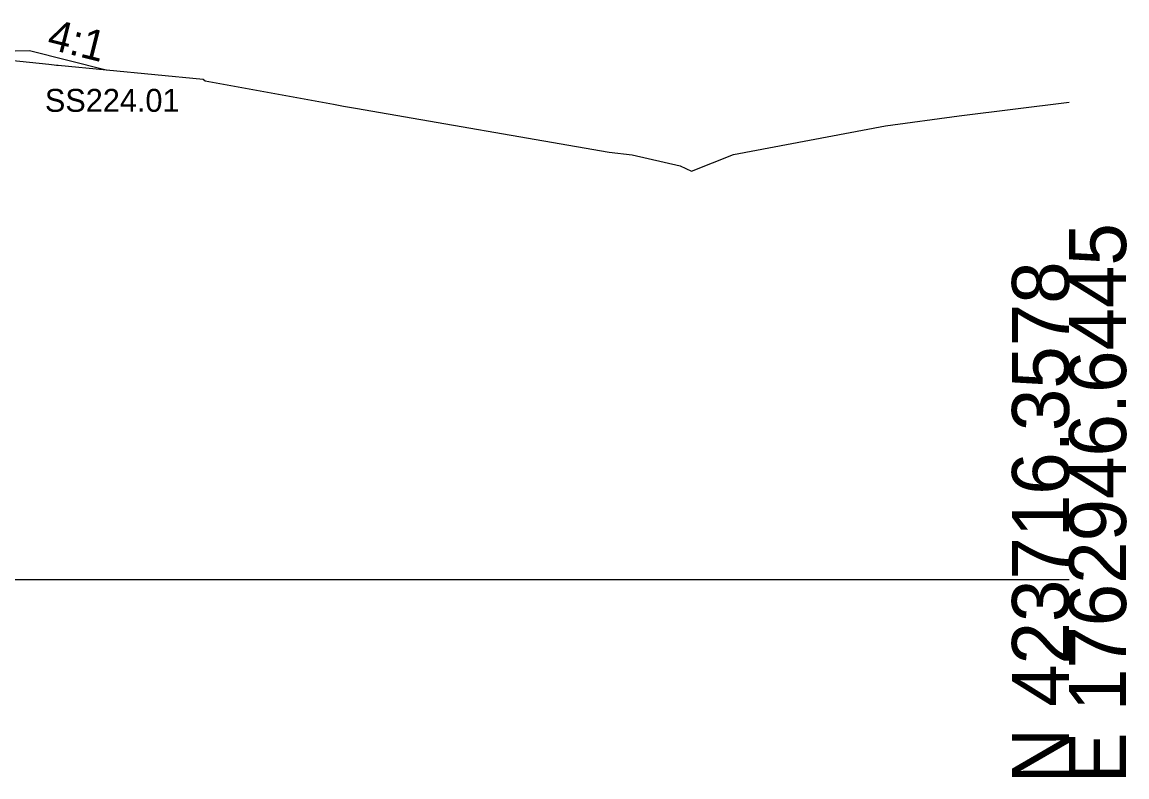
# Model space of a CAD drawing. Extents: x -26 to 3203, y -11010 to 4024.
# Drawn here: x 1148.6 to 1202.8, y -509.7 to -472.6 of the extents above; entities that cross this region are included whole.
import ezdxf

# ---------------------------------------------------------------- set-up
doc = ezdxf.new("R2010")
doc.units = 0
for name, color, linetype in [('Exist Cross Section Cell', 7, 'Continuous'), ('Exist XS Ground Line', 7, 'Continuous'), ('Prop CMT Slope Grass', 7, 'Continuous'), ('Prop XS Side Slope Text', 7, 'Continuous'), ('Prop XS SS Elevation Text', 7, 'Continuous'), ('Scratch_Level_0', 7, 'Continuous')]:
    doc.layers.add(name, color=color, linetype=linetype)

msp = doc.modelspace()

# ---------------------------------------------------------------- linework, layer by layer
at = {"layer": 'Exist Cross Section Cell'}
msp.add_line((1100, -500), (1200, -500), dxfattribs=at)
at = {"layer": 'Exist XS Ground Line'}
msp.add_lwpolyline([(1145.494, -474.255), (1149.934, -474.715), (1150.197, -474.742), (1150.316, -474.755), (1150.381, -474.762), (1150.392, -474.763), (1157.515, -475.441), (1157.604, -475.523), (1163.911, -476.682), (1164.407, -476.772), (1164.989, -476.878), (1177.433, -479.035), (1178.563, -479.163), (1180.913, -479.705), (1181.472, -479.96), (1183.529, -479.15), (1190.991, -477.741), (1194.606, -477.255), (1200, -476.571)], dxfattribs=at)
msp.add_lwpolyline([(1145.494, -474.255), (1149.934, -474.715), (1150.197, -474.742), (1150.316, -474.755), (1150.381, -474.762), (1150.392, -474.763), (1157.515, -475.441), (1157.604, -475.523), (1163.911, -476.682), (1164.407, -476.772), (1164.989, -476.878), (1177.433, -479.035), (1178.563, -479.163), (1180.913, -479.705), (1181.472, -479.96), (1183.529, -479.15), (1190.991, -477.741), (1194.606, -477.255), (1200, -476.571)], dxfattribs=at)
msp.add_lwpolyline([(1145.494, -474.255), (1149.934, -474.715), (1150.197, -474.742), (1150.316, -474.755), (1150.381, -474.762), (1150.392, -474.763), (1157.515, -475.441), (1157.604, -475.523), (1163.911, -476.682), (1164.407, -476.772), (1164.989, -476.878), (1177.433, -479.035), (1178.563, -479.163), (1180.913, -479.705), (1181.472, -479.96), (1183.529, -479.15), (1190.991, -477.741), (1194.606, -477.255), (1200, -476.571)], dxfattribs=at)
msp.add_lwpolyline([(1145.494, -474.255), (1149.934, -474.715), (1150.197, -474.742), (1150.316, -474.755), (1150.381, -474.762), (1150.392, -474.763), (1157.515, -475.441), (1157.604, -475.523), (1163.911, -476.682), (1164.407, -476.772), (1164.989, -476.878), (1177.433, -479.035), (1178.563, -479.163), (1180.913, -479.705), (1181.472, -479.96), (1183.529, -479.15), (1190.991, -477.741), (1194.606, -477.255), (1200, -476.571)], dxfattribs=at)
msp.add_lwpolyline([(1145.494, -474.255), (1149.934, -474.715), (1150.197, -474.742), (1150.316, -474.755), (1150.381, -474.762), (1150.392, -474.763), (1157.515, -475.441), (1157.604, -475.523), (1163.911, -476.682), (1164.407, -476.772), (1164.989, -476.878), (1177.433, -479.035), (1178.563, -479.163), (1180.913, -479.705), (1181.472, -479.96), (1183.529, -479.15), (1190.991, -477.741), (1194.606, -477.255), (1200, -476.571)], dxfattribs=at)
at = {"layer": 'Prop CMT Slope Grass'}
msp.add_lwpolyline([(1145.488, -474.115), (1148.988, -474.045), (1152.76, -474.989)], dxfattribs=at)

# ---------------------------------------------------------------- texts
at = {"layer": 'Exist Cross Section Cell'}
for s, p in [('E 1762946.6445', (1202.8, -510)), ('N 423716.3578', (1200, -510))]:
    msp.add_text(s, height=2.8, rotation=90, dxfattribs=at).set_placement(p)
at = {"layer": 'Prop XS Side Slope Text'}
msp.add_text('4:1', height=1.5, rotation=345.9638, dxfattribs=at).set_placement((1149.793, -473.938))
at = {"layer": 'Prop XS SS Elevation Text'}
msp.add_text('SS224.01', height=1.125, dxfattribs=at).set_placement((1149.746, -477.051))
at = {"layer": 'Scratch_Level_0'}
for s, p in [('RT_CSLP_Pnt', (1148.889, -474.055)), ('Exterior Boundary', (1152.602, -474.999)), ('RT_Slope_Fill', (1152.666, -474.999))]:
    msp.add_text(s, height=0.02, dxfattribs=at).set_placement(p)

doc.saveas('drawing.dxf')
